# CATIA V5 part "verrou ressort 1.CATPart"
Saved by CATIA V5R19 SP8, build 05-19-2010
Part number: verrou ressort 1
Bounding box of the stored display mesh (mm): x 0 to 2, y 0 to 2.5, z -2.5 to 2.5
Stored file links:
  C:\Users\Arthur\Desktop\Catia parts\GLOCK\Ensemble culasse\verrou ressort 1.CATPart
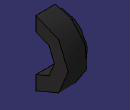
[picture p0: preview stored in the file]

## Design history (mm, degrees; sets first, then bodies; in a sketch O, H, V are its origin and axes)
Set1
  Sketch1 on yz-plane, origin (0, 0, 0), H (0, 1, 0), V (0, 0, 1)
    line L1 (0, 2.5) -> (0, 1.43)
    line L2 (0, -1.43) -> (0, -2.5)
    arc A1 centre (0, 0) radius 1.43 from (0, -1.43) to (0, 1.43) ccw
    arc A2 centre (0, 0) radius 2.5 from (0, -2.5) to (0, 2.5) ccw
    radius A1 = 1.43
    radius A2 = 2.5
    vertical: L1 V, L2 V
    coincidence: L2 V, L1 V
Body1 (main body)
  Pad1: profile Sketch1, direction (1, 0, 0), length 2
  Sketch2 on zx-plane, origin (0, 0, 0), H (-1, 0, 0), V (0, 0, 1)
    circle A1 centre (0, 2.5) radius 0.5
    point P1 (0, 2.5)
    reference projected line E1 (0, 2.5) -> (-2, 2.5) from edge [face of Pad1 from Sketch1.L1 | face of Pad1 from Sketch1.A2]
    radius A1 = 0.5
    coincidence: P1 E1
  Groove1: profile Sketch2, axis Sketch2.H, angle 360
